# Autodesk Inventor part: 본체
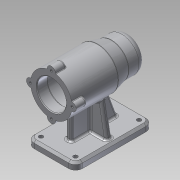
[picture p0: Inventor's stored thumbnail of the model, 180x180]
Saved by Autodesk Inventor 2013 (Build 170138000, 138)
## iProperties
Created: 2019-07
Part Number: 본체
Material: 알루미늄 6061
Document SubType Name: Modeling
Designer: Administrator
Density: 2.71 g/cm^3
Mass: 646.774 g
Surface Area: 654.083 cm^2
Volume: 238.662 cm^3
Author: Administrator
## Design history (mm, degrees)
sketch "스케치1"
  geometry: L1 (0, 0)-(-112, 0); L2 (0, 0)-(0, 30); L3 (0, 30)-(-67, 30); L4 (-67, 30)-(-87, 25); L5 (-87, 25)-(-112, 25); L6 (-112, 25)-(-112, 0); L7 (0, 21)-(-15, 21); L8 (-15, 24)-(-69, 24); L9 (-69, 24)-(-69, 21); L10 (-69, 21)-(-81, 21); L11 (-81, 21)-(-81, 17.5); L12 (-81, 17.5)-(-99, 17.5); L13 (-99, 17.5)-(-99, 16); L14 (-99, 16)-(-103, 16); L15 (-15, 21)-(-15, 24); L16 (-103, 16)-(-103, 10.5); L17 (-103, 10.5)-(-106, 10.5); L18 (-106, 10.5)-(-106, 0); 1 further point
  constraints: 36 end point, 9 horizontal, 8 vertical, 2 point on line, 1 coincident
  dimensions: "d0" = 112 distance of L1.start L1.end; "d2" = 50 diameter of L5 L1; "d3" = 60 diameter of L3 L1; "d4" = 25 distance of L4.end L5.end; "d5" = 45 distance from line of L6 L3.end; "d6" = 42 diameter of L7 L1; "d7" = 48 diameter of L8 L1; "d8" = 42 diameter of L10 L1; "d9" = 35 diameter of L12 L1; "d10" = 32 diameter of L14 L1; "d11" = 21 diameter of L17 L1; "d12" = 3 distance of L16.end L17.end; "d13" = 4 distance of L13.end L14.end; "d14" = 18 distance of L11.end L12.end; "d15" = 12 distance of L9.end L10.end; "d16" = 54 distance of L8.start L8.end; "d17" = 15 distance of L7.start L7.end
revolve "회전1" sketch "스케치1" stored, may be unused: angle "d18" = 90 deg
fillet "모깎기1" dims "d19" = 10
sketch "스케치2"
  geometry: C1 r 21 at (0, 0) reference; C2 r 6 at (30, 0); 1 further point
  constraints: 2 horizontal alignment, 1 centre point, 1 other
  dimensions: "d20" = 12 diameter of C2
extrude "돌출1" join sketch "스케치2" distance "d23" = 16; taper "d24" = 0 deg
hole "구멍1" diameter "d27" = 3.242; stored, may be unused: countersink angle "d31" = 90 deg, drill point angle "d33" = 118 deg; dims "d25" = 10, "d26" = 10, "d28" = 8, "d29" = 4, "d30" = 2, "d32" = 11
node "작업 평면1"
sketch "스케치3"
  geometry: L1 (0, 0)-(56, 0); L2 (56, 0)-(56, -35); L3 (56, -35)-(112, -35); L4 (112, -35)-(112, 35); L5 (112, 35)-(0, 35); L6 (0, 35)-(0, -35); L7 (0, -35)-(56, -35)
  constraints: 14 end point, 3 horizontal, 3 vertical
  dimensions: "d38" = 56 distance of L1.start L1.end; "d39" = 35 distance of L1.end L2.end; "d40" = 56 distance of L2.end L3.end; "d41" = 70 distance of L3.end L4.end; "d42" = 112 distance of L4.end L5.end; "d43" = 70 distance of L5.end L6.end
extrude "돌출2" join sketch "스케치3" distance "d44" = 10; taper "d45" = 0 deg
fillet "모깎기2" dims "d46" = 10
sketch "스케치4"
  geometry: C1 r 3 at (-102, 25); C2 r 3 at (-102, -25); C3 r 3 at (-10, -25); C4 r 3 at (-10, 25); A1 r 10 centre (-102, -25) between (-112, -25) and (-102, -35) reference; A2 r 10 centre (-10, -25) between (-10, -35) and (0, -25) reference; A3 r 10 centre (-10, 25) between (0, 25) and (-10, 35) reference; A4 r 10 centre (-102, 25) between (-102, 35) and (-112, 25) reference; 1 further point
  constraints: 4 centre point, 4 coincident, 3 equal radius
  dimensions: "d47" = 6 diameter of C1
extrude "돌출3" cut sketch "스케치4" stored distance "d49" = 10; taper "d50" = 0 deg
sketch "스케치5"
  geometry: L1 (0, -25)-(0, 25) reference; L2 (-112, 25)-(-112, -25) reference; L3 (-25, -4)-(-92, -4); L4 (-92, -4)-(-92, 4); L5 (-92, 4)-(-25, 4); L6 (-25, 4)-(-25, -4); L7 (-25, -4)-(-92, 4); L8 (-92, -4)-(-25, 4); 4 further points
  constraints: 12 end point, 4 midpoint, 2 parallel, 1 horizontal, 1 horizontal alignment, 1 perpendicular
  dimensions: "d54" = 25 distance between parallel lines of L1 L6; "d55" = 20 distance between parallel lines of L2 L4; "d56" = 8 distance of L3.end L4.end
extrude "돌출4" join sketch "스케치5" stored distance "d57" = 10; taper "d58" = 0 deg
feature "면 기울기1" dims angle "d59" = 20 deg
node "작업 평면2"
sketch "스케치6"
  geometry: L1 (-70, -25)-(-70, 25) reference; L2 (-70, -28)-(-41.732, -23.016); L3 (-70, -35)-(-80, -35) reference; 1 further point
  constraints: 2 end point, 1 point on line
  dimensions: "d61" = 7 distance from line of L3 L2.start; "d62" = 100 deg angle of L1 L2
feature "리브1" sketch "스케치6" dims "d63" = 1, "d64" = 8, "d65" = 0, "d66" = 0, "d67" = 1, "d68" = 1
node "작업 평면3"
sketch "스케치7"
  geometry: L1 (0, 36)-(0, 29.4) reference; 2 further points
  constraints: 1 horizontal alignment, 1 other
  dimensions: "d86" = 42 distance from line of point (-42, 0) L1
feature "엠보싱1" sketch "스케치7" dims "d0" = 112, "d2" = 50, "d3" = 60, "d4" = 25, "d5" = 45, "d6" = 42, "d7" = 48, "d8" = 42, "d9" = 35, "d10" = 32, "d11" = 21, "d12" = 3, "d13" = 4, "d14" = 18, "d15" = 12, "d16" = 54, "d17" = 15, "d71" = 0.5, "d72" = 0
fillet "모깎기3" dims "d73" = 3
fillet "모깎기4" dims "d74" = 1
fillet "모깎기6" dims "d76" = 3
fillet "모깎기12" dims "d83" = 3
fillet "모깎기13" dims "d84" = 3
fillet "모깎기14" dims "d85" = 3, "d87" = 0.3
chamfer "모따기1" distance "d88" = 3; stored, may be unused: second distance "d89" = 2, angle "d90" = 45 deg
fillet "모깎기15" dims "d91" = 3
chamfer "모따기2" distance "d92" = 1; stored, may be unused: second distance "d93" = 2, angle "d94" = 45 deg
node "솔리드1"
pattern_circular "원형 패턴1" dims angle "d35" = 360 deg
mirror "대칭1"
other parameters: "d60" = -56
